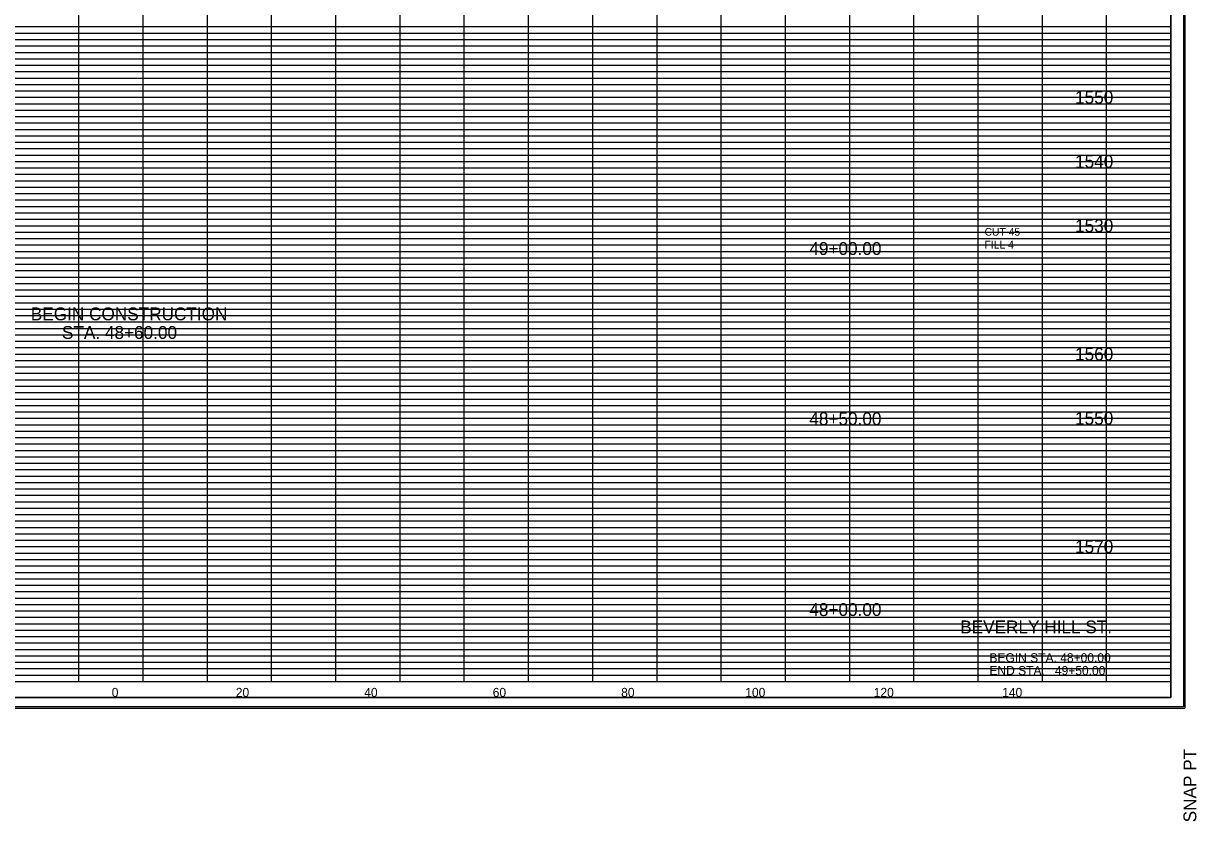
# Model space of a CAD drawing. Extents: x 980 to 1324, y 978 to 1227.
# Drawn here: x 1141.4 to 1324, y 978.2 to 1102.5 of the extents above; entities that cross this region are included whole.
import ezdxf

# ---------------------------------------------------------------- set-up
doc = ezdxf.new("R2010")
doc.units = 0
for name, color, linetype in [('DESIGN - SHEET - Corner Text', 7, 'Continuous'), ('DESIGN - SHEET - Light Grid', 7, 'Continuous'), ('DESIGN - SHEET - Linework', 7, 'Continuous'), ('DESIGN - SHEET - Plot Shape', 7, 'Continuous'), ('DESIGN - TYPICAL - Text', 7, 'Continuous')]:
    doc.layers.add(name, color=color, linetype=linetype)

# ---------------------------------------------------------------- blocks, each defined once
blk = doc.blocks.new('XSTSHT')
at = {"layer": 'DESIGN - SHEET - Light Grid'}
for p, q in [((8, 10.2), (16, 10.2)), ((8, 10.1), (16, 10.1)), ((16, 10.2), (24, 10.2)), ((16, 10.1), (24, 10.1)), ((24, 10.2), (32, 10.2)), ((24, 10.1), (32, 10.1)), ((8, 9.9), (16, 9.9)), ((16, 9.9), (24, 9.9)), ((24, 9.9), (32, 9.9)), ((8, 9.8), (16, 9.8)), ((8, 9.7), (16, 9.7)), ((16, 9.8), (24, 9.8)), ((16, 9.7), (24, 9.7)), ((24, 9.8), (32, 9.8)), ((24, 9.7), (32, 9.7)), ((8, 9.6), (16, 9.6)), ((8, 9.5), (16, 9.5)), ((16, 9.6), (24, 9.6)), ((16, 9.5), (24, 9.5)), ((24, 9.6), (32, 9.6)), ((24, 9.5), (32, 9.5)), ((8, 9.4), (16, 9.4)), ((16, 9.4), (24, 9.4)), ((24, 9.4), (32, 9.4)), ((8, 9.3), (16, 9.3)), ((8, 9.2), (16, 9.2)), ((16, 9.3), (24, 9.3)), ((16, 9.2), (24, 9.2)), ((24, 9.3), (32, 9.3)), ((24, 9.2), (32, 9.2)), ((8, 9.1), (16, 9.1)), ((16, 9.1), (24, 9.1)), ((24, 9.1), (32, 9.1)), ((8, 8.9), (16, 8.9)), ((8, 8.8), (16, 8.8)), ((16, 8.9), (24, 8.9)), ((16, 8.8), (24, 8.8)), ((24, 8.9), (32, 8.9)), ((24, 8.8), (32, 8.8)), ((8, 8.7), (16, 8.7)), ((8, 8.6), (16, 8.6)), ((16, 8.7), (24, 8.7)), ((16, 8.6), (24, 8.6)), ((24, 8.7), (32, 8.7)), ((24, 8.6), (32, 8.6)), ((8, 8.5), (16, 8.5)), ((16, 8.5), (24, 8.5)), ((24, 8.5), (32, 8.5)), ((8, 8.4), (16, 8.4)), ((8, 8.3), (16, 8.3)), ((16, 8.4), (24, 8.4)), ((16, 8.3), (24, 8.3)), ((24, 8.4), (32, 8.4)), ((24, 8.3), (32, 8.3)), ((8, 8.2), (16, 8.2)), ((8, 8.1), (16, 8.1)), ((16, 8.2), (24, 8.2)), ((16, 8.1), (24, 8.1)), ((24, 8.2), (32, 8.2)), ((24, 8.1), (32, 8.1)), ((8, 7.9), (16, 7.9)), ((16, 7.9), (24, 7.9)), ((24, 7.9), (32, 7.9)), ((8, 7.8), (16, 7.8)), ((8, 7.7), (16, 7.7)), ((16, 7.8), (24, 7.8)), ((16, 7.7), (24, 7.7)), ((24, 7.8), (32, 7.8)), ((24, 7.7), (32, 7.7)), ((8, 7.6), (16, 7.6)), ((8, 7.5), (16, 7.5)), ((16, 7.6), (24, 7.6)), ((16, 7.5), (24, 7.5)), ((24, 7.6), (32, 7.6)), ((24, 7.5), (32, 7.5)), ((8, 7.4), (16, 7.4)), ((16, 7.4), (24, 7.4)), ((24, 7.4), (32, 7.4)), ((8, 7.3), (16, 7.3)), ((8, 7.2), (16, 7.2)), ((16, 7.3), (24, 7.3)), ((16, 7.2), (24, 7.2)), ((24, 7.3), (32, 7.3)), ((24, 7.2), (32, 7.2)), ((8, 7.1), (16, 7.1)), ((16, 7.1), (24, 7.1)), ((24, 7.1), (32, 7.1)), ((8, 6.9), (16, 6.9)), ((8, 6.8), (16, 6.8)), ((16, 6.9), (24, 6.9)), ((16, 6.8), (24, 6.8)), ((24, 6.9), (32, 6.9)), ((24, 6.8), (32, 6.8)), ((8, 6.7), (16, 6.7)), ((8, 6.6), (16, 6.6)), ((16, 6.7), (24, 6.7)), ((16, 6.6), (24, 6.6)), ((24, 6.7), (32, 6.7)), ((24, 6.6), (32, 6.6)), ((8, 6.5), (16, 6.5)), ((8, 6.4), (16, 6.4)), ((16, 6.5), (24, 6.5)), ((16, 6.4), (24, 6.4)), ((24, 6.5), (32, 6.5)), ((24, 6.4), (32, 6.4)), ((8, 6.3), (16, 6.3)), ((16, 6.3), (24, 6.3)), ((24, 6.3), (32, 6.3)), ((8, 6.2), (16, 6.2)), ((8, 6.1), (16, 6.1)), ((16, 6.2), (24, 6.2)), ((16, 6.1), (24, 6.1)), ((24, 6.2), (32, 6.2)), ((24, 6.1), (32, 6.1)), ((8, 5.9), (16, 5.9)), ((16, 5.9), (24, 5.9)), ((24, 5.9), (32, 5.9)), ((8, 5.8), (16, 5.8)), ((8, 5.7), (16, 5.7)), ((16, 5.8), (24, 5.8)), ((16, 5.7), (24, 5.7)), ((24, 5.8), (32, 5.8)), ((24, 5.7), (32, 5.7)), ((8, 5.6), (16, 5.6)), ((8, 5.5), (16, 5.5)), ((16, 5.6), (24, 5.6)), ((16, 5.5), (24, 5.5)), ((24, 5.6), (32, 5.6)), ((24, 5.5), (32, 5.5)), ((8, 5.4), (16, 5.4)), ((8, 5.3), (16, 5.3)), ((16, 5.4), (24, 5.4)), ((16, 5.3), (24, 5.3)), ((24, 5.4), (32, 5.4)), ((24, 5.3), (32, 5.3)), ((8, 5.2), (16, 5.2)), ((16, 5.2), (24, 5.2)), ((24, 5.2), (32, 5.2)), ((8, 5.1), (16, 5.1)), ((16, 5.1), (24, 5.1)), ((24, 5.1), (32, 5.1)), ((8, 4.9), (16, 4.9)), ((8, 4.8), (16, 4.8)), ((16, 4.9), (24, 4.9)), ((16, 4.8), (24, 4.8)), ((24, 4.9), (32, 4.9)), ((24, 4.8), (32, 4.8)), ((8, 4.7), (16, 4.7)), ((8, 4.6), (16, 4.6)), ((16, 4.7), (24, 4.7)), ((16, 4.6), (24, 4.6)), ((24, 4.7), (32, 4.7)), ((24, 4.6), (32, 4.6)), ((8, 4.5), (16, 4.5)), ((8, 4.4), (16, 4.4)), ((16, 4.5), (24, 4.5)), ((16, 4.4), (24, 4.4)), ((24, 4.5), (32, 4.5)), ((24, 4.4), (32, 4.4)), ((8, 4.3), (16, 4.3)), ((16, 4.3), (24, 4.3)), ((24, 4.3), (32, 4.3)), ((8, 4.2), (16, 4.2)), ((8, 4.1), (16, 4.1)), ((16, 4.2), (24, 4.2)), ((16, 4.1), (24, 4.1)), ((24, 4.2), (32, 4.2)), ((24, 4.1), (32, 4.1)), ((8, 3.9), (16, 3.9)), ((16, 3.9), (24, 3.9)), ((24, 3.9), (32, 3.9)), ((8, 3.8), (16, 3.8)), ((8, 3.7), (16, 3.7)), ((16, 3.8), (24, 3.8)), ((16, 3.7), (24, 3.7)), ((24, 3.8), (32, 3.8)), ((24, 3.7), (32, 3.7)), ((8, 3.6), (16, 3.6)), ((8, 3.5), (16, 3.5)), ((16, 3.6), (24, 3.6)), ((16, 3.5), (24, 3.5)), ((24, 3.6), (32, 3.6)), ((24, 3.5), (32, 3.5)), ((8, 3.4), (16, 3.4)), ((8, 3.3), (16, 3.3)), ((16, 3.4), (24, 3.4)), ((16, 3.3), (24, 3.3)), ((24, 3.4), (32, 3.4)), ((24, 3.3), (32, 3.3)), ((8, 3.2), (16, 3.2)), ((16, 3.2), (24, 3.2)), ((24, 3.2), (32, 3.2)), ((8, 3.1), (16, 3.1)), ((16, 3.1), (24, 3.1)), ((24, 3.1), (32, 3.1)), ((8, 2.9), (16, 2.9)), ((8, 2.8), (16, 2.8)), ((16, 2.9), (24, 2.9)), ((16, 2.8), (24, 2.8)), ((24, 2.9), (32, 2.9)), ((24, 2.8), (32, 2.8)), ((8, 2.7), (16, 2.7)), ((8, 2.6), (16, 2.6)), ((16, 2.7), (24, 2.7)), ((16, 2.6), (24, 2.6)), ((24, 2.7), (32, 2.7)), ((24, 2.6), (32, 2.6)), ((8, 2.5), (16, 2.5)), ((8, 2.4), (16, 2.4)), ((16, 2.5), (24, 2.5)), ((16, 2.4), (24, 2.4)), ((24, 2.5), (32, 2.5)), ((24, 2.4), (32, 2.4)), ((8, 2.3), (16, 2.3)), ((8, 2.2), (16, 2.2)), ((16, 2.3), (24, 2.3)), ((16, 2.2), (24, 2.2)), ((24, 2.3), (32, 2.3)), ((24, 2.2), (32, 2.2)), ((8, 2.1), (16, 2.1)), ((16, 2.1), (24, 2.1)), ((24, 2.1), (32, 2.1)), ((8, 1.9), (16, 1.9)), ((16, 1.9), (24, 1.9)), ((24, 1.9), (32, 1.9)), ((8, 1.8), (16, 1.8)), ((8, 1.7), (16, 1.7)), ((16, 1.8), (24, 1.8)), ((16, 1.7), (24, 1.7)), ((24, 1.8), (32, 1.8)), ((24, 1.7), (32, 1.7)), ((8, 1.6), (16, 1.6)), ((8, 1.5), (16, 1.5)), ((16, 1.6), (24, 1.6)), ((16, 1.5), (24, 1.5)), ((24, 1.6), (32, 1.6)), ((24, 1.5), (32, 1.5)), ((8, 1.4), (16, 1.4)), ((8, 1.3), (16, 1.3)), ((16, 1.4), (24, 1.4)), ((16, 1.3), (24, 1.3)), ((24, 1.4), (32, 1.4)), ((24, 1.3), (32, 1.3)), ((8, 1.2), (16, 1.2)), ((8, 1.1), (16, 1.1)), ((16, 1.2), (24, 1.2)), ((16, 1.1), (24, 1.1)), ((24, 1.2), (32, 1.2)), ((24, 1.1), (32, 1.1)), ((8, 0.9), (16, 0.9)), ((8, 0.8), (16, 0.8)), ((16, 0.9), (24, 0.9)), ((16, 0.8), (24, 0.8)), ((24, 0.9), (32, 0.9)), ((24, 0.8), (32, 0.8)), ((8, 0.7), (16, 0.7)), ((8, 0.6), (16, 0.6)), ((16, 0.7), (24, 0.7)), ((16, 0.6), (24, 0.6)), ((24, 0.7), (32, 0.7)), ((24, 0.6), (32, 0.6)), ((8, 0.5), (16, 0.5)), ((8, 0.4), (16, 0.4)), ((16, 0.5), (24, 0.5)), ((16, 0.4), (24, 0.4)), ((24, 0.5), (32, 0.5)), ((24, 0.4), (32, 0.4)), ((8, 0.3), (16, 0.3)), ((8, 0.2), (16, 0.2)), ((16, 0.3), (24, 0.3)), ((16, 0.2), (24, 0.2)), ((24, 0.3), (32, 0.3)), ((24, 0.2), (32, 0.2)), ((8, 0.1), (16, 0.1)), ((16, 0.1), (24, 0.1)), ((24, 0.1), (32, 0.1))]:
    blk.add_line(p, q, dxfattribs=at)
at = {"layer": 'DESIGN - SHEET - Linework'}
for p, q in [((32.217, 21.414), (32.217, -0.414)), ((15, 0), (15, 21)), ((16, 0), (16, 21)), ((17, 0), (17, 21)), ((18, 0), (18, 21)), ((19, 0), (19, 21)), ((20, 0), (20, 21)), ((21, 0), (21, 21)), ((22, 0), (22, 21)), ((23, 0), (23, 21)), ((24, 0), (24, 21)), ((25, 0), (25, 21)), ((26, 0), (26, 21)), ((27, 0), (27, 21)), ((28, 0), (28, 20)), ((29, 0), (29, 20)), ((30, 0), (30, 20)), ((31, 0), (31, 20)), ((0, 10), (32, 10)), ((0, 9), (32, 9)), ((0, 8), (32, 8)), ((0, 7), (32, 7)), ((0, 6), (32, 6)), ((0, 5), (32, 5)), ((0, 4), (32, 4)), ((0, 3), (32, 3)), ((0, 2), (32, 2)), ((0, 1), (32, 1)), ((-1.823, -0.414), (32.217, -0.414))]:
    blk.add_line(p, q, dxfattribs=at)
blk.add_lwpolyline([(0, 21), (0, 0), (32, 0), (32, 21), (0, 21)], dxfattribs=at)
at = {"layer": 'DESIGN - SHEET - Plot Shape'}
for points in [[(-1.803, 21.394), (32.197, 21.394), (32.197, -0.394), (-1.803, -0.394)], [(-0.85, 21), (32, 21), (32, -0.25), (-0.85, -0.25)]]:
    blk.add_lwpolyline(points, close=True, dxfattribs=at)
at = {"layer": 'DESIGN - SHEET - Corner Text'}
blk.add_text('SNAP PT  ', height=0.2, rotation=90, dxfattribs=at).set_placement((32.397, -2.194))

msp = doc.modelspace()

# ---------------------------------------------------------------- linework, layer by layer
at = {"layer": 'DESIGN - SHEET - Plot Shape'}
msp.add_lwpolyline([(991.5, 997.5), (1320, 997.5), (1320, 1210), (991.5, 1210)], close=True, dxfattribs=at)

# ---------------------------------------------------------------- block references
at = {"layer": 'DESIGN - TYPICAL - Text', "xscale": 10, "yscale": 10}
msp.add_blockref('XSTSHT', (1000, 1000), dxfattribs=at)

# ---------------------------------------------------------------- texts
at = {"layer": 'DESIGN - SHEET - Corner Text'}
for s, height, p in [('BEVERLY HILL ST.', 2, (1287.21, 1007.5)), ('BEGIN STA. 48+00.00', 1.4, (1291.75, 1003)), ('END STA.   49+50.00', 1.4, (1291.75, 1001))]:
    msp.add_text(s, height=height, dxfattribs=at).set_placement(p)
at = {"layer": 'DESIGN - TYPICAL - Text'}
for s, height, p in [('     1550     ', 2, (1301.37, 1090)), ('     1540     ', 2, (1301.37, 1080)), ('CUT 45', 1.2, (1291, 1069.44)), ('     1530     ', 2, (1301.37, 1070)), ('     49+00.00     ', 2, (1260, 1066.44)), ('FILL 4', 1.2, (1291, 1067.44)), ('BEGIN CONSTRUCTION', 2, (1142.51, 1056.26)), ('STA. 48+60.00', 2, (1147.36, 1053.36)), ('     1560     ', 2, (1301.37, 1050)), ('     48+50.00     ', 2, (1260, 1039.93)), ('     1550     ', 2, (1301.37, 1040)), ('     1570     ', 2, (1301.37, 1020)), ('     48+00.00     ', 2, (1260, 1010.2)), ('     0     ', 1.4, (1152.51, 997.6)), ('     0     ', 1.4, (1152.51, 997.6)), ('     20     ', 1.4, (1171.82, 997.6)), ('     40     ', 1.4, (1191.82, 997.6)), ('     60     ', 1.4, (1211.82, 997.6)), ('     80     ', 1.4, (1231.82, 997.6)), ('     100     ', 1.4, (1251.14, 997.6)), ('     120     ', 1.4, (1271.14, 997.6)), ('     140     ', 1.4, (1291.14, 997.6))]:
    msp.add_text(s, height=height, dxfattribs=at).set_placement(p)

doc.saveas('drawing.dxf')
